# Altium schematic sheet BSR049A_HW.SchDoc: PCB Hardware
size 431 x 279 mm; Date: Not shown in title block; ApprovedBy: Not shown in title block; CheckedBy: Not shown in title block; Author: Not shown in title block; CompanyName: Not shown in title block; DrawnBy: K Nielson; Engineer: Not shown in title block; Organization: Not shown in title block; Address1: Not shown in title block; Address2: Not shown in title block; Address3: Not shown in title block; Address4: Not shown in title block; DocumentNumber: 1; Revision: Use project parameter SCH_Rev; SheetNumber: 3; SheetTotal: 3; PageSetup: Record=PageOptions¦CenterHorizontal=True¦CenterVertical=True¦PrintScale=1.00¦XCorrection=1.00¦YCorrection=1.00¦PrintKind=0¦BorderSize=5000000¦LeftOffset=0¦BottomOffset=0¦Orientation=2¦PaperLength=1000¦PaperWidth=1000¦Scale=100¦PaperSource=15¦PrintQuality=600¦MediaType=1¦DitherType=10¦PaperKind=Letter¦PrintScaleMode=1
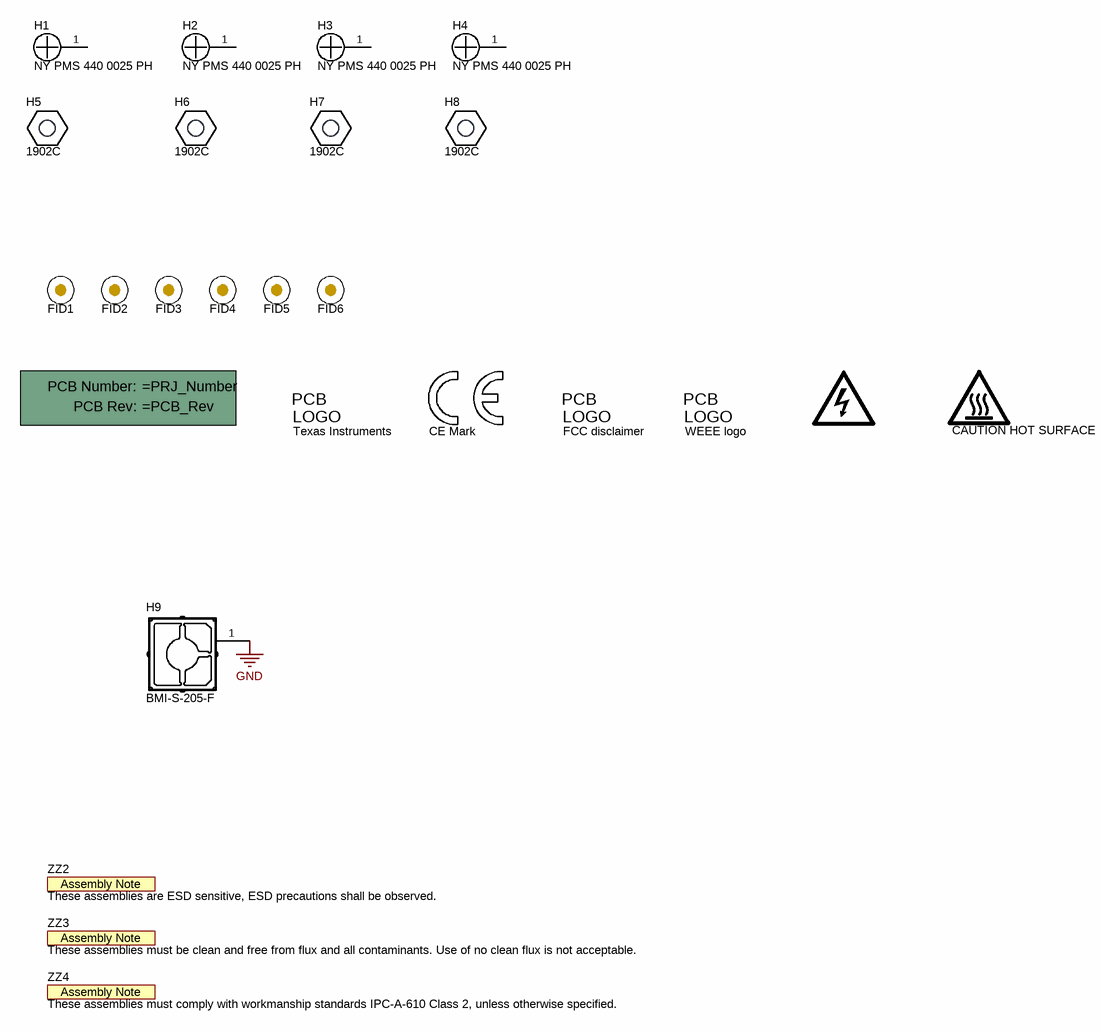
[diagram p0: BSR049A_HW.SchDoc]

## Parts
!PCB  Printed Circuit Board  (value not drawn)  (mechanical)
FID1  Fiducial  [Fiducial10-20]  (value not drawn)
FID2  Fiducial  [Fiducial10-20]  (value not drawn)
FID3  Fiducial  [Fiducial10-20]  (value not drawn)
FID4  Fiducial  [Fiducial10-20]  (value not drawn)
FID5  Fiducial  [Fiducial10-20]  (value not drawn)
FID6  Fiducial  [Fiducial10-20]  (value not drawn)
H1  NY PMS 440 0025 PH  [NY PMS 440 0025 PH]
H2  NY PMS 440 0025 PH  [NY PMS 440 0025 PH]
H3  NY PMS 440 0025 PH  [NY PMS 440 0025 PH]
H4  NY PMS 440 0025 PH  [NY PMS 440 0025 PH]
H5  1902C  [Keystone_1902C]
H6  1902C  [Keystone_1902C]
H7  1902C  [Keystone_1902C]
H8  1902C  [Keystone_1902C]
H9  BMI-S-205-F  [Laird_BMI-S-205-F]
Logo1  Texas Instruments  [TI_Stacked_Overlay_Small]  (no BOM)
Logo2  CE Mark  [CE_Mark_5mm]  (no BOM)
Logo3  FCC disclaimer  [FCC_disclaimer]  (no BOM)
Logo4  WEEE logo  [WEEE_Minimum]  (no BOM)
Logo5  DANGER HIGH VOLTAGE  [IEC_HighVoltage_Small]  (value not drawn)  (no BOM)
Logo6  CAUTION HOT SURFACE  [IEC_HotSurface_Small]  (no BOM)
ZZ2  These assemblies are ESD sensitive, ESD precautions shall be observed.  [AssemblyNote]  (no BOM)
ZZ3  These assemblies must be clean and free from flux and all contaminants. Use of no clean flux is not acceptable.  [AssemblyNote]  (no BOM)
ZZ4  These assemblies must comply with workmanship standards IPC-A-610 Class 2, unless otherwise specified.  [AssemblyNote]  (no BOM)

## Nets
GND: H9.1

Not connected (* = marked no-connect by the designer): H1 1; H2 1; H3 1; H4 1

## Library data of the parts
!PCB = CMP-0003618-2: Manufacturer: Any
FID1-FID6 = CMP-0077181-1: Fiducial mark.  There is nothing to buy or mount.
H1-H4 = CMP-0003617-1: Machine Screw, Round, #4-40 x 1/4, Nylon, Philips panhead; Manufacturer: B&F Fastener Supply; CompType: Hardware
H5-H8 = CMP-0003610-1: Standoff, Hex, 0.5"L #4-40 Nylon; Manufacturer: Keystone; CompType: Hardware
H9 = CMP-0003954-1: Standard Surface Mount Shield, 38.1 x 25.4 mm, Height 6 mm; Manufacturer: Laird-Signal Integrity Products; CompType: Hardware
Logo1 = CMP-0074838-1: Texas Instrument Corporate Signature; SymbolCreator: a0412235; Lib Reference: TI_Logo; Library Reference: Logo
Logo2 = CMP-0074844-1: SymbolCreator: a0412235
Logo3 = CMP-0074847-1: FCC_disclaimer; Library Reference: Logo
Logo4 = CMP-0074769-1
Logo5 = CMP-0074835-1: IEC 61010-1 High Voltage Warning; SymbolCreator: a0412235
Logo6 = CMP-0074837-1: IEC 61010-1 Hot Surface Warning; SymbolCreator: a0412235
ZZ2 = CMP-0077236-1
ZZ3 = CMP-0077237-1
ZZ4 = CMP-0077238-1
